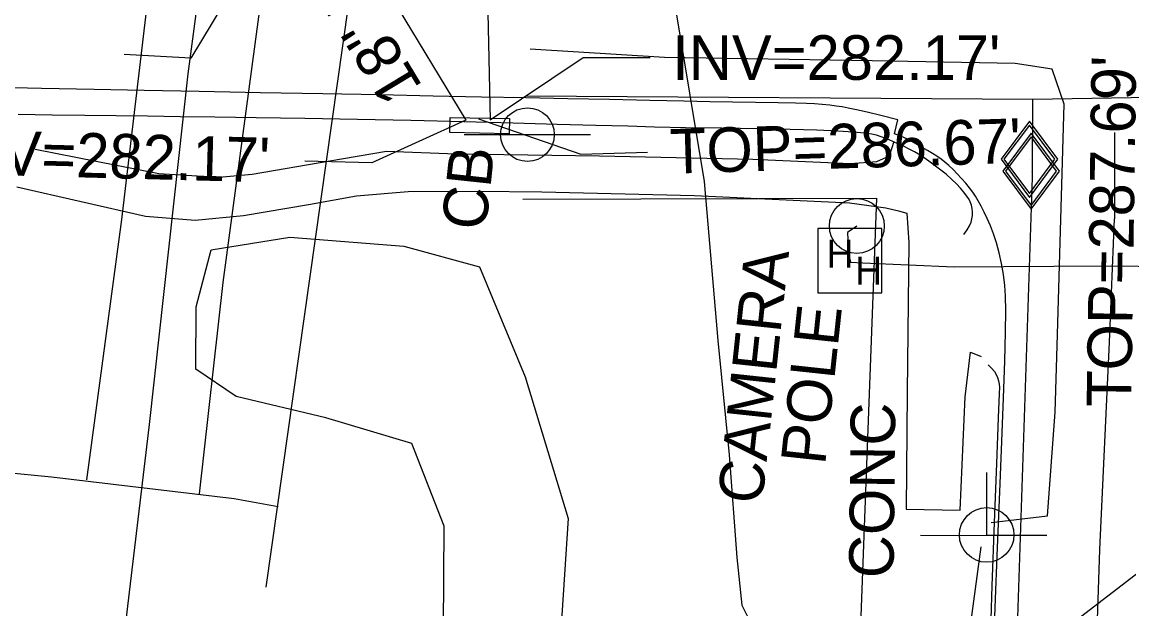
# Model space of a CAD drawing. Extents: x 2100323 to 2109811, y 740376 to 749755.
# Drawn here: x 2105017.1 to 2105116.4, y 742082.9 to 742135.6 of the extents above; entities that cross this region are included whole.
import ezdxf

# ---------------------------------------------------------------- set-up
doc = ezdxf.new("R2010")
doc.units = 0
for name, color, linetype in [('Exist Railroads Standard Gauge', 7, 'Continuous'), ('Exist Right of Way Line', 7, 'Continuous'), ('Exist Roads Curbs', 7, 'Continuous'), ('Exist Roads EOP', 7, 'Continuous'), ('Exist Roads EOP Other', 7, 'Continuous'), ('Exist Roads EOP Other Text', 7, 'Continuous'), ('Exist Structure Major Bridge WW', 7, 'Continuous'), ('Exist Structure Major Deck Tunnel Box Culvert', 7, 'Continuous'), ('Exist Structure Minor Catch Basin', 7, 'Continuous'), ('Exist Structure Minor Catch Basin Text', 7, 'Continuous'), ('Exist Structure Minor Catch Basin Top Elevation', 7, 'Continuous'), ('Exist Structure Minor Pipes RCP 18 Inch', 7, 'Continuous'), ('Exist Structure Minor Pipes RCP 18 Inch Invert', 7, 'Continuous'), ('Exist Structure Minor Pipes RCP 18 Inch Leader', 7, 'Continuous'), ('Exist Structure Minor Pipes RCP 18 Inch Text', 7, 'Continuous'), ('Exist Structure Minor Pipes RCP 30 Inch Invert', 7, 'Continuous'), ('Exist Utilities Gas UG Line SUE LOS B', 7, 'Continuous'), ('Exist Utilities Gas Valve CELL', 7, 'Continuous'), ('Exist Utilities Other Pole CELL', 7, 'Continuous'), ('Exist Utilities Other Pole Text', 7, 'Continuous'), ('Exist Utilities Other Unknown UG SUE LOS B', 7, 'Continuous'), ('Exist Utilities Power Hand Hole CELL', 7, 'Continuous'), ('Exist Utilities Power Joint Use Telephone CELL', 7, 'Continuous'), ('Exist Utilities Power UG Cable SUE LOS B', 7, 'Continuous'), ('Exist Utilities Sanitary Sewer Manhole Text', 7, 'Continuous'), ('Exist Utilities Telephone Pole CELL', 7, 'Continuous'), ('Exist Utilities Telephone UG Conduit SUE LOS B', 7, 'Continuous'), ('Exist Utilities Telephone UG FO SUE LOS C', 7, 'Continuous'), ('Exist Utilities TV UG Cable SUE LOS B', 7, 'Continuous'), ('Exist Vegetation Hedge Row', 7, 'Continuous')]:
    doc.layers.add(name, color=color, linetype=linetype)

msp = doc.modelspace()

# ---------------------------------------------------------------- linework, layer by layer
at = {"layer": 'Exist Railroads Standard Gauge'}
msp.add_lwpolyline([(2105019.475, 742023.118), (2105022.431, 742048.903), (2105025.549, 742074.137), (2105028.575, 742099.469), (2105032.03, 742130.925), (2105033.658, 742143.071)], dxfattribs=at)
at = {"layer": 'Exist Right of Way Line'}
for p in [(2105062.047, 742119.693), (2105081.094, 741783.714)]:
    msp.add_line(p, (2105093.802, 742119.779), dxfattribs=at)
at = {"layer": 'Exist Roads Curbs'}
for points in [[(2105101.602, 742116.523), (2105101.903, 742116.943), (2105102.122, 742117.313), (2105102.246, 742117.618), (2105102.328, 742117.921), (2105102.375, 742118.231), (2105102.384, 742118.545), (2105102.351, 742118.857), (2105102.278, 742119.165), (2105102.172, 742119.455), (2105102.035, 742119.725), (2105101.85, 742120.005), (2105101.599, 742120.327), (2105101.286, 742120.687), (2105100.928, 742121.069), (2105100.528, 742121.469), (2105100.013, 742121.928), (2105099.308, 742122.485), (2105098.459, 742123.108), (2105097.735, 742123.6), (2105097.181, 742123.927), (2105096.71, 742124.17), (2105096.235, 742124.408), (2105095.753, 742124.643), (2105095.244, 742124.873), (2105094.707, 742125.099), (2105094.194, 742125.294), (2105093.761, 742125.432), (2105093.358, 742125.522), (2105092.689, 742125.611), (2105091.703, 742125.705), (2105090.308, 742125.796), (2105088.41, 742125.874), (2105086.016, 742125.939), (2105083.172, 742125.997), (2105079.886, 742126.05), (2105076.627, 742126.104), (2105073.865, 742126.165), (2105071.463, 742126.233), (2105068.6, 742126.314), (2105065.139, 742126.408), (2105061.167, 742126.512), (2105056.77, 742126.624), (2105052.006, 742126.74), (2105047.23, 742126.841), (2105042.503, 742126.924), (2105038.131, 742126.992), (2105034.424, 742127.048), (2105031.312, 742127.095), (2105028.389, 742127.132), (2105025.586, 742127.162), (2105022.78, 742127.195), (2105019.85, 742127.24), (2105016.79, 742127.296)], [(2105103.772, 742104.833), (2105104.107, 742104.508), (2105104.346, 742104.223), (2105104.497, 742103.97), (2105104.614, 742103.698), (2105104.705, 742103.397), (2105104.765, 742103.089), (2105104.79, 742102.794), (2105104.774, 742102.272), (2105104.688, 742100.079), (2105104.529, 742095.974), (2105104.329, 742090.702), (2105104.125, 742085.007), (2105103.917, 742079.019)]]:
    msp.add_lwpolyline(points, dxfattribs=at)
at = {"layer": 'Exist Roads EOP'}
msp.add_lwpolyline([(2105104.226, 742077.87), (2105104.42, 742083.071), (2105104.63, 742088.451), (2105104.828, 742093.441), (2105105.01, 742097.947), (2105105.163, 742101.88), (2105105.271, 742105.153), (2105105.335, 742107.765), (2105105.356, 742109.712), (2105105.336, 742110.995), (2105105.268, 742111.956), (2105105.148, 742112.939), (2105104.978, 742113.932), (2105104.773, 742114.877), (2105104.536, 742115.763), (2105104.274, 742116.577), (2105103.993, 742117.303), (2105103.697, 742117.947), (2105103.415, 742118.532), (2105103.15, 742119.064), (2105102.897, 742119.538), (2105102.652, 742119.954), (2105102.406, 742120.321), (2105102.113, 742120.706), (2105101.767, 742121.121), (2105101.392, 742121.544), (2105101.012, 742121.954), (2105100.632, 742122.347), (2105100.263, 742122.7), (2105099.91, 742123.01), (2105099.554, 742123.288), (2105099.18, 742123.543), (2105098.783, 742123.784), (2105098.33, 742124.055), (2105097.815, 742124.363), (2105097.308, 742124.662), (2105096.877, 742124.906), (2105096.495, 742125.105), (2105096.004, 742125.316), (2105095.377, 742125.549), (2105095.683, 742126.806), (2105094.158, 742127.204), (2105092.929, 742127.503), (2105091.983, 742127.71), (2105091.236, 742127.865), (2105090.674, 742127.972), (2105090.162, 742128.051), (2105089.567, 742128.121), (2105088.897, 742128.181), (2105088.206, 742128.234), (2105087.503, 742128.28), (2105086.513, 742128.318), (2105084.962, 742128.347), (2105082.925, 742128.369), (2105080.856, 742128.398), (2105078.83, 742128.437), (2105076.482, 742128.487), (2105073.449, 742128.549), (2105069.812, 742128.623), (2105066.073, 742128.699), (2105062.313, 742128.777), (2105058.351, 742128.858), (2105054.003, 742128.947), (2105049.265, 742129.042), (2105044.111, 742129.142), (2105038.535, 742129.246), (2105033.031, 742129.349), (2105028.089, 742129.442), (2105023.599, 742129.53), (2105018.887, 742129.625), (2105013.842, 742129.73)], dxfattribs=at)
at = {"layer": 'Exist Roads EOP Other'}
for points in [[(2105018.327, 742124.173), (2105029.404, 742121.997), (2105034.809, 742121.682), (2105037.759, 742121.939), (2105044.732, 742123.147), (2105049.816, 742124.011), (2105056.071, 742123.762), (2105068.939, 742123.58), (2105082.677, 742123.288), (2105091.446, 742122.898), (2105093.809, 742123.068), (2105094.943, 742123.58), (2105095.353, 742124.911)], [(2105016.678, 742120.787), (2105028.22, 742118.178), (2105032.67, 742117.809), (2105036.988, 742118.229), (2105042.818, 742119.213), (2105047.127, 742120.001), (2105051.765, 742120.379), (2105057.917, 742120.399), (2105063.764, 742120.346), (2105077.454, 742120.014), (2105091.332, 742119.376), (2105094.601, 742118.932), (2105095.75, 742118.662), (2105096.48, 742118.424), (2105096.666, 742115.822), (2105096.523, 742102.371), (2105096.424, 742091.876), (2105101.283, 742091.791), (2105101.716, 742101.948), (2105102.193, 742105.956), (2105103.158, 742105.578)]]:
    msp.add_lwpolyline(points, dxfattribs=at)
at = {"layer": 'Exist Structure Major Bridge WW'}
msp.add_lwpolyline([(2105040.105, 742092.107), (2105036.164, 742092.806), (2105019.767, 742094.756), (2105015.506, 742095.17)], dxfattribs=at)
at = {"layer": 'Exist Structure Major Deck Tunnel Box Culvert'}
for points in [[(2105022.956, 742094.514), (2105026.087, 742117.867), (2105029.094, 742143.413), (2105032.155, 742163.318), (2105034.856, 742183.272), (2105037.769, 742201.552), (2105039.052, 742209.31)], [(2105048.504, 742207.616), (2105043.459, 742171.412), (2105038.336, 742136.039), (2105035.138, 742112.216), (2105033.024, 742093.253)]]:
    msp.add_lwpolyline(points, dxfattribs=at)
at = {"layer": 'Exist Structure Minor Catch Basin'}
msp.add_lwpolyline([(2105055.523, 742127.019), (2105060.849, 742126.917), (2105060.824, 742125.564), (2105055.497, 742125.666)], close=True, dxfattribs=at)
at = {"layer": 'Exist Structure Minor Catch Basin Top Elevation'}
msp.add_lwpolyline([(2105058.077, 742126.908), (2105067.246, 742123.724), (2105073.243, 742123.911)], dxfattribs=at)
at = {"layer": 'Exist Structure Minor Pipes RCP 18 Inch'}
for p, q in [((2105058, 742176.004), (2105059.124, 742126.812)), ((2105040.87, 742153.347), (2105056.922, 742126.778))]:
    msp.add_line(p, q, dxfattribs=at)
at = {"layer": 'Exist Structure Minor Pipes RCP 18 Inch Leader'}
for points in [[(2105059.124, 742126.812), (2105067.455, 742132.4), (2105073.455, 742132.4)], [(2105056.922, 742126.778), (2105048.503, 742122.952), (2105042.505, 742123.112)]]:
    msp.add_lwpolyline(points, dxfattribs=at)
at = {"layer": 'Exist Structure Minor Pipes RCP 30 Inch Invert'}
msp.add_lwpolyline([(2105044.706, 742152.974), (2105032.28, 742132.349), (2105026.289, 742132.672)], dxfattribs=at)
at = {"layer": 'Exist Utilities Gas UG Line SUE LOS B'}
for points in [[(2105062.324, 742128.96), (2105107.794, 742128.656), (2105167.748, 742129.669), (2105219.556, 742129.918), (2105221.378, 742149.484), (2105223.8, 742181.971), (2105228.159, 742215.323), (2105233.434, 742244.914), (2105243.497, 742283), (2105255.93, 742322.901)], [(2105091.741, 741682.837), (2105095.231, 741757.886), (2105099.13, 741876.227), (2105103.49, 741993.335), (2105107.757, 742121.648), (2105107.794, 742128.656)]]:
    msp.add_lwpolyline(points, dxfattribs=at)
at = {"layer": 'Exist Utilities Gas Valve CELL'}
for p, q in [((2105107.477, 742123.271), (2105107.477, 742123.271)), ((2105107.631, 742122.199), (2105107.631, 742122.199))]:
    msp.add_line(p, q, dxfattribs=at)
for points in [[(2105107.477, 742126.684), (2105104.939, 742123.271), (2105107.477, 742119.859), (2105110.015, 742123.271), (2105107.477, 742126.684)], [(2105107.631, 742125.612), (2105105.093, 742122.199), (2105107.631, 742118.787), (2105110.169, 742122.199), (2105107.631, 742125.612)]]:
    msp.add_lwpolyline(points, dxfattribs=at)
for points in [[(2105109.765, 742123.271), (2105107.477, 742126.348), (2105105.189, 742123.271), (2105107.477, 742120.194)], [(2105109.919, 742122.199), (2105107.631, 742125.277), (2105105.343, 742122.199), (2105107.631, 742119.122)]]:
    msp.add_lwpolyline(points, close=True, dxfattribs=at)
at = {"layer": 'Exist Utilities Other Pole CELL'}
msp.add_circle((2105092.005, 742117.286), 2.463, dxfattribs=at)
at = {"layer": 'Exist Utilities Other Unknown UG SUE LOS B'}
msp.add_line((2105115.125, 742125.681), (2105115.106, 742117.932), dxfattribs=at)
msp.add_lwpolyline([(2105101.007, 741760.827), (2105101.612, 741785.543), (2105102.335, 741802.493), (2105103.813, 741828.967), (2105104.625, 741853.104), (2105105.37, 741876.451), (2105106.531, 741901.387), (2105107.65, 741927.712), (2105108.522, 741953.384), (2105109.451, 741978.733), (2105111.23, 742031.894), (2105112.93, 742062.173), (2105113.807, 742088.278), (2105114.657, 742106.87), (2105115.106, 742117.932)], dxfattribs=at)
at = {"layer": 'Exist Utilities Power Hand Hole CELL'}
msp.add_line((2105091.448, 742114.031), (2105091.448, 742114.031), dxfattribs=at)
msp.add_lwpolyline([(2105088.498, 742111.306), (2105094.248, 742111.306), (2105094.248, 742117.056), (2105088.498, 742117.056), (2105088.498, 742111.306)], dxfattribs=at)
at = {"layer": 'Exist Utilities Power Joint Use Telephone CELL'}
msp.add_line((2105103.647, 742089.563), (2105103.647, 742089.563), dxfattribs=at)
msp.add_lwpolyline([(2105097.709, 742089.563), (2105109.047, 742089.526), (2105103.647, 742089.544), (2105103.647, 742095.188)], dxfattribs=at)
msp.add_circle((2105103.648, 742089.57), 2.45, dxfattribs=at)
at = {"layer": 'Exist Utilities Power UG Cable SUE LOS B'}
for p, q in [((2105092.006, 742117.286), (2105091.151, 742116.693)), ((2105091.151, 742116.693), (2105091.255, 742114.79))]:
    msp.add_line(p, q, dxfattribs=at)
for points in [[(2105091.255, 742114.79), (2105091.448, 742114.031), (2105092.549, 742113.98)], [(2105092.549, 742113.98), (2105100.74, 742113.612), (2105114.138, 742113.705), (2105129.651, 742113.554), (2105141.351, 742114.259)]]:
    msp.add_lwpolyline(points, dxfattribs=at)
at = {"layer": 'Exist Utilities Telephone Pole CELL'}
for p, q in [((2105056.784, 742125.485), (2105068.121, 742125.485)), ((2105062.459, 742125.485), (2105062.459, 742125.485))]:
    msp.add_line(p, q, dxfattribs=at)
msp.add_circle((2105062.459, 742125.485), 2.407, dxfattribs=at)
at = {"layer": 'Exist Utilities Telephone UG Conduit SUE LOS B'}
for points in [[(2105103.131, 742088.495), (2105101.009, 742072.786), (2105111.685, 742081.926), (2105146.141, 742108.414), (2105186.571, 742138.69), (2105209.148, 742157.951), (2105240.685, 742192.748), (2105255.444, 742191.892), (2105405.101, 742191.496), (2105465.373, 742191.697), (2105498.782, 742193.465), (2105569.455, 742194.912), (2105579.793, 742194.992), (2105583.832, 742193.798), (2105587.319, 742190.308), (2105620.453, 742190.951), (2105664.049, 742170.377), (2105679.452, 742164.298), (2105754.897, 742133.713), (2105860.555, 742098.34), (2105944.571, 742073.094)], [(2105104.036, 742090.677), (2105109.107, 742091.277), (2105109.784, 742100.591), (2105110.007, 742107.565), (2105110.599, 742128.228), (2105109.519, 742131.37), (2105106.19, 742131.851), (2105093.376, 742132.111), (2105074.763, 742132.405), (2105062.698, 742133.154)]]:
    msp.add_lwpolyline(points, dxfattribs=at)
at = {"layer": 'Exist Utilities Telephone UG FO SUE LOS C'}
msp.add_lwpolyline([(2105039.037, 742084.874), (2105055.27, 742199.566), (2105066.583, 742285.216)], dxfattribs=at)
at = {"layer": 'Exist Utilities TV UG Cable SUE LOS B'}
msp.add_lwpolyline([(2105048.663, 742179.038), (2105063.619, 742179.754), (2105064.836, 742179.663), (2105066.638, 742179.226), (2105067.398, 742176.998), (2105073.027, 742153.189), (2105078.306, 742121.279), (2105079.538, 742107.011), (2105080.562, 742096.746), (2105081.248, 742087.56), (2105081.679, 742083.268), (2105083.132, 742080.386), (2105087.94, 742075.447), (2105093.728, 742069.225)], dxfattribs=at)
at = {"layer": 'Exist Vegetation Hedge Row'}
msp.add_lwpolyline([(2105054.882, 742072.102), (2105054.984, 742090.35), (2105052.094, 742097.785), (2105044.375, 742100.09), (2105036.328, 742101.98), (2105032.718, 742104.456), (2105032.754, 742110.036), (2105034.097, 742115.164), (2105041.142, 742116.296), (2105051.385, 742115.486), (2105058.15, 742113.628), (2105062.261, 742103.742), (2105066.111, 742091.045), (2105065.112, 742075.518)], dxfattribs=at)

# ---------------------------------------------------------------- texts
at = {"layer": 'Exist Roads EOP Other Text'}
msp.add_text('CONC', height=4, rotation=89.39291, dxfattribs=at).set_placement((2105095.294, 742085.678))
at = {"layer": 'Exist Structure Minor Catch Basin Text'}
msp.add_text('CB', height=4, rotation=83.88645, dxfattribs=at).set_placement((2105058.724, 742116.806))
at = {"layer": 'Exist Structure Minor Catch Basin Top Elevation'}
msp.add_text("TOP=286.67'", height=4, rotation=1.78787, dxfattribs=at).set_placement((2105075.304, 742121.975))
at = {"layer": 'Exist Structure Minor Pipes RCP 18 Inch Invert'}
msp.add_text("INV=282.17'", height=4, dxfattribs=at).set_placement((2105075.455, 742130.4))
msp.add_text("INV=282.17'", height=4, rotation=358.46974, dxfattribs=at).set_placement((2105009.912, 742121.982))
at = {"layer": 'Exist Structure Minor Pipes RCP 18 Inch Text'}
msp.add_text('18" RCP', height=4, rotation=121.13957, dxfattribs=at).set_placement((2105053.107, 742129.779))
at = {"layer": 'Exist Utilities Other Pole Text'}
for s, p in [('CAMERA', (2105083.497, 742092.248)), ('POLE', (2105089.155, 742095.776))]:
    msp.add_text(s, height=4, rotation=83.88645, dxfattribs=at).set_placement(p)
at = {"layer": 'Exist Utilities Power Hand Hole CELL'}
for p in [(2105089.289, 742113.557), (2105091.853, 742112.036)]:
    msp.add_text('H', height=2.5, dxfattribs=at).set_placement(p)
at = {"layer": 'Exist Utilities Sanitary Sewer Manhole Text'}
msp.add_text("TOP=287.69'", height=4, rotation=89.18205, dxfattribs=at).set_placement((2105116.61, 742101.036))

doc.saveas('drawing.dxf')
